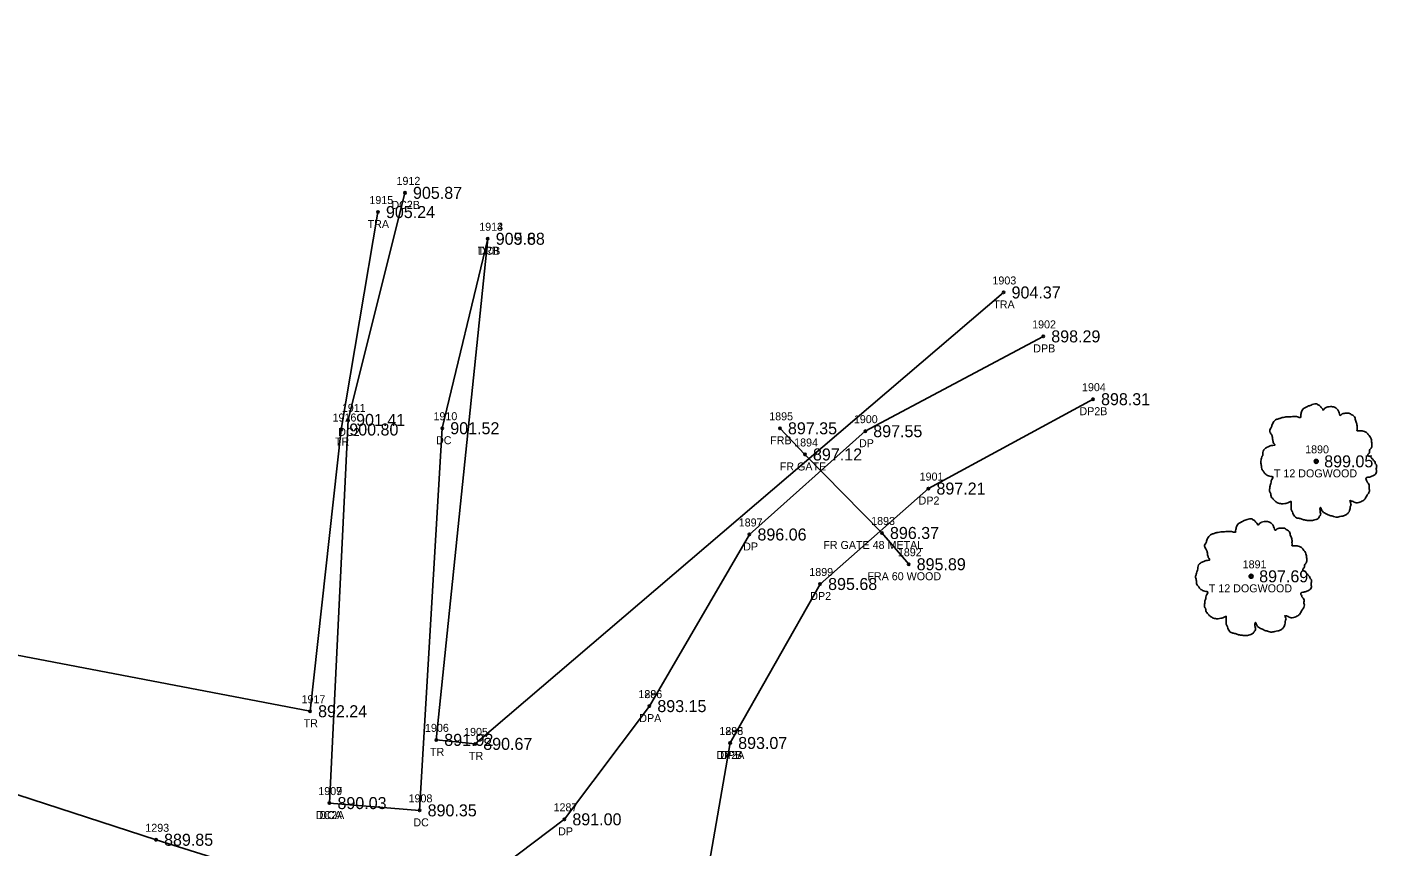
# Model space of a CAD drawing. Extents: x 1448136 to 1453623, y 1125056 to 1128842.
# Drawn here: x 1449466.4 to 1449636, y 1126859.8 to 1126962.3 of the extents above; entities that cross this region are included whole.
import ezdxf

# ---------------------------------------------------------------- set-up
doc = ezdxf.new("R2010")
doc.units = 0
for name, color, linetype in [('RD_EX_Conc', 7, 'Continuous'), ('RD_EX_Conc_txCode', 7, 'Continuous'), ('RD_EX_Driveway', 7, 'Continuous'), ('RD_EX_Driveway_txCode', 7, 'Continuous'), ('RD_EX_Fence_Other', 7, 'Continuous'), ('RD_EX_Fence_Other_txCode', 7, 'Continuous'), ('RD_EX_Road', 7, 'Continuous'), ('RD_EX_Road_txCode', 7, 'Continuous'), ('RD_EX_TX_Conc_ELEV', 7, 'Continuous'), ('RD_EX_TX_Driveway_ELEV', 7, 'Continuous'), ('RD_EX_TX_Fence_Other_ELEV', 7, 'Continuous'), ('RD_EX_TX_Road_ELEV', 7, 'Continuous'), ('RD_EX_TX_VEG_ELEV', 7, 'Continuous'), ('RD_EX_VEG', 7, 'Continuous'), ('RD_EX_VEG_txCode', 7, 'Continuous'), ('RD_SMD_Locator', 7, 'Continuous')]:
    doc.layers.add(name, color=color, linetype=linetype)

msp = doc.modelspace()

# ---------------------------------------------------------------- linework, layer by layer
at = {"layer": 'RD_EX_Conc'}
for points in [[(1449504.21, 1126865.27), (1449506.54, 1126913.16), (1449513.65, 1126941.54)], [(1449504.21, 1126865.27), (1449515.48, 1126864.36), (1449518.31, 1126912.12), (1449523.99, 1126935.8)]]:
    msp.add_lwpolyline(points, dxfattribs=at)
at = {"layer": 'RD_EX_Driveway'}
for points in [[(1449544.19, 1126877.39), (1449556.7, 1126898.84), (1449571.17, 1126911.75), (1449593.42, 1126923.6)], [(1449554.29, 1126872.78), (1449565.53, 1126892.65), (1449579.07, 1126904.58), (1449599.64, 1126915.75)], [(1449544.19, 1126877.39), (1449533.57, 1126863.24), (1449524.04, 1126856.06), (1449511.24, 1126851.67)], [(1449569.21, 1126834.03), (1449555.75, 1126842.94), (1449551.33, 1126855.74), (1449554.29, 1126872.78)]]:
    msp.add_lwpolyline(points, dxfattribs=at)
at = {"layer": 'RD_EX_Fence_Other'}
msp.add_lwpolyline([(1449576.6, 1126895.12), (1449573.26, 1126899.03), (1449563.64, 1126908.84), (1449560.51, 1126912.11)], dxfattribs=at)
at = {"layer": 'RD_EX_Road'}
msp.add_lwpolyline([(1450334.81, 1126677.22), (1450288.34, 1126667.77), (1450239.92, 1126662.52), (1450192.72, 1126661.45), (1450145.26, 1126665.09), (1450097.34, 1126672.81), (1450049.7, 1126684.25), (1450007.41, 1126696.7), (1449955.88, 1126712.65), (1449909.23, 1126727.21), (1449862.31, 1126741.85), (1449813.73, 1126756.84), (1449766.18, 1126771.72), (1449717.33, 1126787.19), (1449671.79, 1126801.4), (1449624.98, 1126815.8), (1449576.84, 1126830.74), (1449569.21, 1126834.03), (1449511.24, 1126851.67), (1449482.54, 1126860.68), (1449432.31, 1126877.02)], dxfattribs=at)
at = {"layer": 'RD_EX_VEG'}
for points in [[(1449510.27, 1126939.14), (1449505.69, 1126911.96), (1449501.79, 1126876.75), (1449433.99, 1126889.72), (1449367.41, 1126918.51), (1449395.05, 1126962.25)], [(1449588.46, 1126929.09), (1449522.43, 1126872.67), (1449517.56, 1126873.17), (1449523.99, 1126935.8)]]:
    msp.add_lwpolyline(points, dxfattribs=at)
for centre, radius in [((1449627.53, 1126907.98), 0.25), ((1449627.52, 1126907.96), 0.0001), ((1449619.4, 1126893.61), 0.25), ((1449619.39, 1126893.59), 0.0001)]:
    msp.add_circle(centre, radius, dxfattribs=at)
for points in [[(1449627.66, 1126915.15), (1449627.36, 1126915.17), (1449627.04, 1126915.07), (1449626.79, 1126914.97), (1449626.56, 1126914.9), (1449626.34, 1126914.8), (1449626.04, 1126914.62), (1449625.81, 1126914.42), (1449625.69, 1126914.17), (1449625.64, 1126913.95), (1449625.59, 1126913.67), (1449625.59, 1126913.5), (1449625.46, 1126913.47), (1449625.31, 1126913.5), (1449625.06, 1126913.57), (1449624.81, 1126913.57), (1449624.56, 1126913.57), (1449624.21, 1126913.55), (1449623.86, 1126913.55), (1449623.59, 1126913.5), (1449623.27, 1126913.45), (1449622.89, 1126913.32), (1449622.54, 1126913.2), (1449622.24, 1126912.95), (1449621.99, 1126912.47), (1449621.87, 1126912.12), (1449621.72, 1126911.87), (1449621.87, 1126911.42), (1449622.04, 1126911.07), (1449622.07, 1126910.87), (1449622.14, 1126910.45), (1449622.24, 1126910.22), (1449622.37, 1126910.02), (1449622.29, 1126910), (1449621.92, 1126909.95), (1449621.62, 1126909.85), (1449621.19, 1126909.62), (1449620.97, 1126909.4), (1449620.87, 1126909.07), (1449620.84, 1126908.73), (1449620.74, 1126908.53), (1449620.67, 1126908.25), (1449620.64, 1126908.18), (1449620.59, 1126907.85), (1449620.69, 1126907.4), (1449620.72, 1126907.05), (1449620.84, 1126906.83), (1449620.99, 1126906.65), (1449621.17, 1126906.4), (1449621.57, 1126906.18), (1449621.89, 1126906.08), (1449622.09, 1126906.05), (1449621.92, 1126905.55), (1449621.87, 1126905.2), (1449621.74, 1126904.8), (1449621.74, 1126904.73), (1449621.69, 1126904.25), (1449621.84, 1126903.93), (1449621.92, 1126903.55), (1449622.09, 1126903.33), (1449622.37, 1126903.03), (1449622.69, 1126902.8), (1449623.19, 1126902.68), (1449623.59, 1126902.7), (1449624.16, 1126902.88), (1449624.41, 1126902.95), (1449624.39, 1126902.78), (1449624.41, 1126902.4), (1449624.41, 1126901.98), (1449624.56, 1126901.65), (1449624.66, 1126901.38), (1449624.81, 1126901.13), (1449625.14, 1126900.9), (1449625.54, 1126900.83), (1449625.96, 1126900.68), (1449626.41, 1126900.6), (1449626.91, 1126900.58), (1449627.51, 1126900.73), (1449627.79, 1126900.85), (1449627.89, 1126901.03), (1449628.09, 1126901.4), (1449628.04, 1126901.63), (1449628.06, 1126902.23), (1449628.16, 1126902.05), (1449628.34, 1126901.7), (1449628.84, 1126901.4), (1449629.24, 1126901.23), (1449629.71, 1126901.08), (1449630.01, 1126901), (1449630.49, 1126901.08), (1449630.86, 1126901.15), (1449631.24, 1126901.28), (1449631.54, 1126901.55), (1449631.71, 1126901.83), (1449631.76, 1126902.1), (1449631.84, 1126902.48), (1449631.89, 1126902.65)], [(1449631.89, 1126902.65), (1449631.81, 1126902.83), (1449631.76, 1126903.08), (1449631.84, 1126903.05), (1449632.01, 1126903), (1449632.29, 1126902.88), (1449632.51, 1126902.8), (1449632.84, 1126902.83), (1449633.11, 1126902.93), (1449633.56, 1126903.2), (1449633.84, 1126903.68), (1449634.11, 1126904.08), (1449634.19, 1126904.4), (1449634.14, 1126904.63), (1449634.11, 1126905.13), (1449633.91, 1126905.38), (1449633.86, 1126905.5), (1449633.76, 1126905.9), (1449633.84, 1126905.95), (1449634.11, 1126906), (1449634.49, 1126906.13), (1449634.76, 1126906.25), (1449634.99, 1126906.43), (1449635.06, 1126906.65), (1449635.04, 1126907.05), (1449635.08, 1126907.45), (1449635.01, 1126907.6), (1449634.91, 1126907.75), (1449634.84, 1126907.95), (1449634.69, 1126908.1), (1449634.59, 1126908.25), (1449634.49, 1126908.35), (1449634.36, 1126908.5), (1449634.19, 1126908.63), (1449634.04, 1126908.68), (1449633.99, 1126908.83), (1449634.14, 1126909.02), (1449634.19, 1126909.12), (1449634.21, 1126909.35), (1449634.44, 1126909.7), (1449634.49, 1126910.1), (1449634.44, 1126910.52), (1449634.39, 1126910.8), (1449634.24, 1126911.07), (1449634.04, 1126911.32), (1449633.91, 1126911.5), (1449633.74, 1126911.62), (1449633.41, 1126911.75), (1449633.16, 1126911.8), (1449632.81, 1126911.8), (1449632.61, 1126911.85), (1449632.64, 1126911.9), (1449632.64, 1126912.05), (1449632.64, 1126912.32), (1449632.56, 1126912.77), (1449632.41, 1126913.27), (1449632.41, 1126913.3), (1449632.31, 1126913.55), (1449632.09, 1126913.75), (1449631.91, 1126913.85), (1449631.71, 1126913.97), (1449631.46, 1126914), (1449631.16, 1126914), (1449630.89, 1126913.95), (1449630.69, 1126913.85), (1449630.51, 1126913.72), (1449630.44, 1126913.87), (1449630.34, 1126914.17), (1449630.29, 1126914.32), (1449630.14, 1126914.5), (1449629.91, 1126914.7), (1449629.46, 1126914.82), (1449628.84, 1126914.75), (1449628.54, 1126914.55), (1449628.39, 1126914.37), (1449628.34, 1126914.5), (1449628.14, 1126914.7), (1449628.04, 1126914.87), (1449627.86, 1126915), (1449627.71, 1126915.1), (1449627.61, 1126915.15)], [(1449619.53, 1126900.78), (1449619.23, 1126900.81), (1449618.91, 1126900.71), (1449618.66, 1126900.61), (1449618.43, 1126900.53), (1449618.21, 1126900.43), (1449617.91, 1126900.26), (1449617.68, 1126900.06), (1449617.56, 1126899.81), (1449617.51, 1126899.58), (1449617.46, 1126899.31), (1449617.46, 1126899.13), (1449617.33, 1126899.11), (1449617.18, 1126899.13), (1449616.93, 1126899.21), (1449616.68, 1126899.21), (1449616.43, 1126899.21), (1449616.08, 1126899.18), (1449615.73, 1126899.18), (1449615.46, 1126899.13), (1449615.13, 1126899.08), (1449614.76, 1126898.96), (1449614.41, 1126898.83), (1449614.11, 1126898.58), (1449613.86, 1126898.11), (1449613.73, 1126897.76), (1449613.59, 1126897.51), (1449613.73, 1126897.06), (1449613.91, 1126896.71), (1449613.93, 1126896.51), (1449614.01, 1126896.08), (1449614.11, 1126895.86), (1449614.23, 1126895.66), (1449614.16, 1126895.63), (1449613.78, 1126895.58), (1449613.49, 1126895.48), (1449613.06, 1126895.26), (1449612.84, 1126895.03), (1449612.74, 1126894.71), (1449612.71, 1126894.36), (1449612.61, 1126894.16), (1449612.54, 1126893.88), (1449612.51, 1126893.81), (1449612.46, 1126893.48), (1449612.56, 1126893.03), (1449612.59, 1126892.68), (1449612.71, 1126892.46), (1449612.86, 1126892.28), (1449613.04, 1126892.03), (1449613.44, 1126891.81), (1449613.76, 1126891.71), (1449613.96, 1126891.68), (1449613.78, 1126891.18), (1449613.73, 1126890.83), (1449613.61, 1126890.43), (1449613.61, 1126890.36), (1449613.56, 1126889.88), (1449613.71, 1126889.56), (1449613.78, 1126889.19), (1449613.96, 1126888.96), (1449614.23, 1126888.66), (1449614.56, 1126888.44), (1449615.06, 1126888.31), (1449615.46, 1126888.34), (1449616.03, 1126888.51), (1449616.28, 1126888.59), (1449616.26, 1126888.41), (1449616.28, 1126888.04), (1449616.28, 1126887.61), (1449616.43, 1126887.29), (1449616.53, 1126887.01), (1449616.68, 1126886.76), (1449617.01, 1126886.54), (1449617.41, 1126886.46), (1449617.83, 1126886.31), (1449618.28, 1126886.24), (1449618.78, 1126886.21), (1449619.38, 1126886.36), (1449619.66, 1126886.49), (1449619.76, 1126886.66), (1449619.96, 1126887.04), (1449619.91, 1126887.26), (1449619.93, 1126887.86), (1449620.03, 1126887.69), (1449620.21, 1126887.34), (1449620.71, 1126887.04), (1449621.11, 1126886.86), (1449621.58, 1126886.71), (1449621.88, 1126886.64), (1449622.36, 1126886.71), (1449622.73, 1126886.79), (1449623.11, 1126886.91), (1449623.41, 1126887.19), (1449623.58, 1126887.46), (1449623.63, 1126887.74), (1449623.71, 1126888.11), (1449623.76, 1126888.29)], [(1449623.76, 1126888.29), (1449623.68, 1126888.46), (1449623.63, 1126888.71), (1449623.71, 1126888.69), (1449623.88, 1126888.64), (1449624.16, 1126888.51), (1449624.38, 1126888.44), (1449624.71, 1126888.46), (1449624.98, 1126888.56), (1449625.43, 1126888.84), (1449625.7, 1126889.31), (1449625.98, 1126889.71), (1449626.05, 1126890.03), (1449626, 1126890.26), (1449625.98, 1126890.76), (1449625.78, 1126891.01), (1449625.73, 1126891.13), (1449625.63, 1126891.53), (1449625.7, 1126891.58), (1449625.98, 1126891.63), (1449626.35, 1126891.76), (1449626.63, 1126891.88), (1449626.85, 1126892.06), (1449626.93, 1126892.28), (1449626.9, 1126892.68), (1449626.95, 1126893.08), (1449626.88, 1126893.23), (1449626.78, 1126893.38), (1449626.7, 1126893.58), (1449626.55, 1126893.73), (1449626.45, 1126893.88), (1449626.35, 1126893.98), (1449626.23, 1126894.13), (1449626.05, 1126894.26), (1449625.9, 1126894.31), (1449625.85, 1126894.46), (1449626, 1126894.66), (1449626.05, 1126894.76), (1449626.08, 1126894.98), (1449626.3, 1126895.33), (1449626.35, 1126895.73), (1449626.3, 1126896.16), (1449626.25, 1126896.43), (1449626.1, 1126896.71), (1449625.9, 1126896.96), (1449625.78, 1126897.13), (1449625.6, 1126897.26), (1449625.28, 1126897.38), (1449625.03, 1126897.43), (1449624.68, 1126897.43), (1449624.48, 1126897.48), (1449624.51, 1126897.53), (1449624.51, 1126897.68), (1449624.51, 1126897.96), (1449624.43, 1126898.41), (1449624.28, 1126898.91), (1449624.28, 1126898.93), (1449624.18, 1126899.18), (1449623.96, 1126899.38), (1449623.78, 1126899.48), (1449623.58, 1126899.61), (1449623.33, 1126899.63), (1449623.03, 1126899.63), (1449622.76, 1126899.58), (1449622.56, 1126899.48), (1449622.38, 1126899.36), (1449622.31, 1126899.51), (1449622.21, 1126899.81), (1449622.16, 1126899.96), (1449622.01, 1126900.13), (1449621.78, 1126900.33), (1449621.33, 1126900.46), (1449620.71, 1126900.38), (1449620.41, 1126900.18), (1449620.26, 1126900.01), (1449620.21, 1126900.13), (1449620.01, 1126900.33), (1449619.91, 1126900.51), (1449619.73, 1126900.63), (1449619.58, 1126900.73), (1449619.48, 1126900.78)]]:
    msp.add_spline(points, degree=3, dxfattribs=at)
at = {"layer": 'RD_SMD_Locator'}
for centre in [(1449513.65, 1126941.54), (1449510.27, 1126939.14), (1449523.99, 1126935.8), (1449523.99, 1126935.8), (1449588.46, 1126929.09), (1449593.42, 1126923.6), (1449599.64, 1126915.75), (1449506.54, 1126913.16), (1449505.69, 1126911.96), (1449518.31, 1126912.12), (1449560.51, 1126912.11), (1449571.17, 1126911.75), (1449563.64, 1126908.84), (1449627.53, 1126907.98), (1449579.07, 1126904.58), (1449573.26, 1126899.03), (1449556.7, 1126898.84), (1449576.6, 1126895.12), (1449565.53, 1126892.65), (1449619.4, 1126893.61), (1449544.19, 1126877.39), (1449544.19, 1126877.39), (1449501.79, 1126876.75), (1449517.56, 1126873.17), (1449522.43, 1126872.67), (1449554.29, 1126872.78), (1449554.29, 1126872.78), (1449504.21, 1126865.27), (1449504.21, 1126865.27), (1449515.48, 1126864.36), (1449533.57, 1126863.24), (1449482.54, 1126860.68)]:
    msp.add_circle(centre, 0.15, dxfattribs=at)

# ---------------------------------------------------------------- texts
at = {"layer": 'RD_EX_Conc_txCode'}
for s, p in [('1912', (1449512.59, 1126942.54)), ('DC2B', (1449511.95, 1126939.54)), ('1913', (1449522.93, 1126936.8)), ('DCB', (1449522.74, 1126933.8)), ('1911', (1449505.76, 1126914.16)), ('1910', (1449517.21, 1126913.12)), ('DC2', (1449505.31, 1126911.16)), ('DC', (1449517.53, 1126910.12)), ('1907', (1449502.82, 1126866.27)), ('1909', (1449502.82, 1126866.27)), ('1908', (1449514.1, 1126865.36)), ('DC2A', (1449502.49, 1126863.27)), ('DCA', (1449502.94, 1126863.27)), ('DC', (1449514.7, 1126862.36))]:
    msp.add_text(s, height=1, dxfattribs=at).set_placement(p)
at = {"layer": 'RD_EX_Driveway_txCode'}
for s, p in [('1902', (1449592.03, 1126924.6)), ('DPB', (1449592.17, 1126921.6)), ('1904', (1449598.26, 1126916.75)), ('DP2B', (1449597.94, 1126913.75)), ('1900', (1449569.75, 1126912.75)), ('DP', (1449570.39, 1126909.75)), ('1901', (1449577.97, 1126905.58)), ('DP2', (1449577.84, 1126902.58)), ('1897', (1449555.36, 1126899.84)), ('DP', (1449555.92, 1126896.84)), ('1899', (1449564.18, 1126893.65)), ('DP2', (1449564.3, 1126890.65)), ('1286', (1449542.82, 1126878.39)), ('1896', (1449542.82, 1126878.39)), ('DPA', (1449542.93, 1126875.39)), ('DPA', (1449542.93, 1126875.39)), ('1285', (1449552.94, 1126873.78)), ('1898', (1449552.94, 1126873.78)), ('DP2A', (1449552.57, 1126870.78)), ('DPB', (1449553.03, 1126870.78)), ('1287', (1449532.22, 1126864.24)), ('DP', (1449532.79, 1126861.24))]:
    msp.add_text(s, height=1, dxfattribs=at).set_placement(p)
at = {"layer": 'RD_EX_Fence_Other_txCode'}
for s, p in [('1895', (1449559.17, 1126913.11)), ('FRB', (1449559.29, 1126910.11)), ('1894', (1449562.29, 1126909.84)), ('FR GATE', (1449560.49, 1126906.84)), ('1893', (1449571.91, 1126900.03)), ('FR GATE 48 METAL', (1449565.93, 1126897.03)), ('1892', (1449575.25, 1126896.12)), ('FRA 60 WOOD', (1449571.44, 1126893.12))]:
    msp.add_text(s, height=1, dxfattribs=at).set_placement(p)
at = {"layer": 'RD_EX_Road_txCode'}
msp.add_text('1293', height=1, dxfattribs=at).set_placement((1449481.2, 1126861.68))
at = {"layer": 'RD_EX_TX_Conc_ELEV'}
for s, p in [('905.87', (1449514.65, 1126940.79)), ('905.88', (1449524.99, 1126935.05)), ('901.41', (1449507.54, 1126912.41)), ('901.52', (1449519.31, 1126911.37)), ('890.03', (1449505.21, 1126864.52)), ('890.03', (1449505.21, 1126864.52)), ('890.35', (1449516.48, 1126863.61))]:
    msp.add_text(s, height=1.5, dxfattribs=at).set_placement(p)
at = {"layer": 'RD_EX_TX_Driveway_ELEV'}
for s, p in [('898.29', (1449594.42, 1126922.85)), ('898.31', (1449600.64, 1126915)), ('897.55', (1449572.17, 1126911)), ('897.21', (1449580.07, 1126903.83)), ('896.06', (1449557.7, 1126898.09)), ('895.68', (1449566.53, 1126891.9)), ('893.15', (1449545.19, 1126876.64)), ('893.15', (1449545.19, 1126876.64)), ('893.07', (1449555.29, 1126872.03)), ('893.07', (1449555.29, 1126872.03)), ('891.00', (1449534.57, 1126862.49))]:
    msp.add_text(s, height=1.5, dxfattribs=at).set_placement(p)
at = {"layer": 'RD_EX_TX_Fence_Other_ELEV'}
for s, p in [('897.35', (1449561.51, 1126911.36)), ('897.12', (1449564.64, 1126908.09)), ('896.37', (1449574.26, 1126898.28)), ('895.89', (1449577.6, 1126894.37))]:
    msp.add_text(s, height=1.5, dxfattribs=at).set_placement(p)
at = {"layer": 'RD_EX_TX_Road_ELEV'}
msp.add_text('889.85', height=1.5, dxfattribs=at).set_placement((1449483.54, 1126859.93))
at = {"layer": 'RD_EX_TX_VEG_ELEV'}
for s, p in [('905.24', (1449511.27, 1126938.39)), ('909.68', (1449524.99, 1126935.05)), ('904.37', (1449589.46, 1126928.34)), ('900.80', (1449506.69, 1126911.21)), ('899.05', (1449628.53, 1126907.23)), ('897.69', (1449620.4, 1126892.86)), ('892.24', (1449502.79, 1126876)), ('891.92', (1449518.56, 1126872.42)), ('890.67', (1449523.43, 1126871.92))]:
    msp.add_text(s, height=1.5, dxfattribs=at).set_placement(p)
at = {"layer": 'RD_EX_VEG_txCode'}
for s, p in [('1915', (1449509.2, 1126940.14)), ('TRA', (1449508.98, 1126937.14)), ('1914', (1449522.93, 1126936.8)), ('TRB', (1449522.73, 1126933.8)), ('1903', (1449587.07, 1126930.09)), ('TRA', (1449587.17, 1126927.09)), ('1916', (1449504.6, 1126912.96)), ('TR', (1449504.9, 1126909.96)), ('1890', (1449626.15, 1126908.98)), ('T 12 DOGWOOD', (1449622.24, 1126905.98)), ('1891', (1449618.34, 1126894.61)), ('T 12 DOGWOOD', (1449614.11, 1126891.61)), ('1917', (1449500.72, 1126877.75)), ('TR', (1449500.99, 1126874.75)), ('1906', (1449516.15, 1126874.17)), ('1905', (1449521.04, 1126873.67)), ('TR', (1449516.77, 1126871.17)), ('TR', (1449521.64, 1126870.67))]:
    msp.add_text(s, height=1, dxfattribs=at).set_placement(p)

doc.saveas('drawing.dxf')
